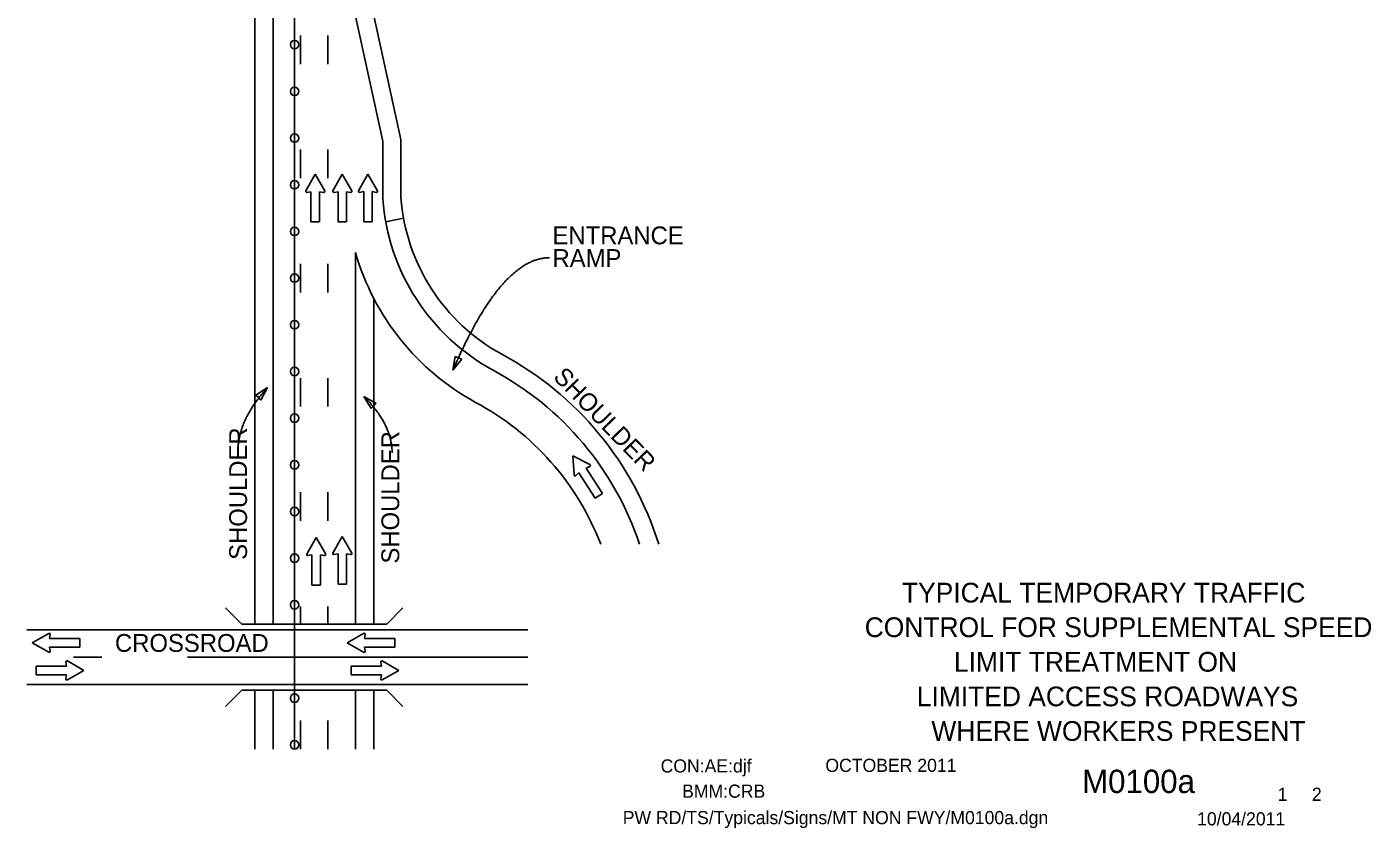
# Model space of a CAD drawing. Extents: x 16115 to 18454, y 4946 to 8326.
# Drawn here: x 16792 to 17425, y 7218 to 7596 of the extents above; entities that cross this region are included whole.
import ezdxf

# ---------------------------------------------------------------- set-up
doc = ezdxf.new("R2010")
doc.units = 0
for name, color, linetype in [('BORDER', 7, 'Continuous'), ('BORDER_SIGNAL_WO', 7, 'Continuous'), ('MT_SCRATCH_LEVEL_E', 7, 'Continuous'), ('PAVT_EDGE_EX', 7, 'Continuous'), ('SCRATCH_LEVEL_A', 7, 'Continuous'), ('TRAFFIC_SIGNS_PR', 7, 'Continuous')]:
    doc.layers.add(name, color=color, linetype=linetype)

msp = doc.modelspace()

# ---------------------------------------------------------------- linework, layer by layer
at = {"layer": 'BORDER'}
for p, q in [((16961.22, 7503.82), (16969.66, 7505.53)), ((16993.91, 7440.44), (16992.85, 7433.9)), ((16995.46, 7439.74), (16993.91, 7440.44)), ((16997.01, 7439.05), (16995.46, 7439.74)), ((16992.85, 7433.9), (16997.01, 7439.05)), ((16905.56, 7425.72), (16899.98, 7422.15)), ((16899.98, 7422.15), (16901.23, 7421.01)), ((16901.23, 7421.01), (16902.48, 7419.86)), ((16902.48, 7419.86), (16905.56, 7425.72)), ((16950.98, 7421.53), (16954.31, 7415.8)), ((16956.71, 7418.2), (16950.98, 7421.53)), ((16954.31, 7415.8), (16955.51, 7417)), ((16955.51, 7417), (16956.71, 7418.2))]:
    msp.add_line(p, q, dxfattribs=at)
msp.add_lwpolyline([(16918.32, 7255.33), (16918.32, 8189.12)], dxfattribs=at)
for centre in [(16918.32, 7587.33), (16918.32, 7565.33), (16918.32, 7543.33), (16918.32, 7521.33), (16918.32, 7499.33), (16918.32, 7477.33), (16918.32, 7455.33), (16918.32, 7433.33), (16918.32, 7411.33), (16918.32, 7389.33), (16918.32, 7367.33), (16918.32, 7345.33), (16918.32, 7323.33), (16918.32, 7279.33), (16918.32, 7257.33)]:
    msp.add_circle(centre, 2, dxfattribs=at)
for points in [[(16992.89, 7433.94), (17015.61, 7486.89), (17038.33, 7486.89)], [(16905.56, 7425.72), (16891.59, 7410.52), (16891.59, 7395.33)], [(16950.98, 7421.53), (16964.25, 7408.25), (16964.25, 7394.98)]]:
    msp.add_open_spline(points, degree=2, dxfattribs=at)
at = {"layer": 'MT_SCRATCH_LEVEL_E'}
for p, q in [((16928.03, 7526.22), (16923.6, 7518.43)), ((16932.49, 7518.43), (16928.03, 7526.22)), ((16940.76, 7526.22), (16936.34, 7518.43)), ((16945.22, 7518.43), (16940.76, 7526.22)), ((16952.85, 7526.26), (16948.43, 7518.46)), ((16957.32, 7518.46), (16952.85, 7526.26)), ((16924.12, 7517.7), (16926.03, 7518.04)), ((16926.03, 7518.04), (16926.03, 7503.77)), ((16930.06, 7503.77), (16930.06, 7518.04)), ((16930.06, 7518.04), (16931.97, 7517.7)), ((16936.85, 7517.7), (16938.77, 7518.04)), ((16938.77, 7518.04), (16938.77, 7503.77)), ((16942.79, 7503.77), (16942.79, 7518.04)), ((16942.79, 7518.04), (16944.71, 7517.7)), ((16948.95, 7517.73), (16950.86, 7518.07)), ((16950.86, 7518.07), (16950.86, 7503.8)), ((16954.89, 7503.8), (16954.89, 7518.07)), ((16954.89, 7518.07), (16956.8, 7517.73)), ((16926.03, 7503.77), (16930.06, 7503.77)), ((16938.77, 7503.77), (16942.79, 7503.77)), ((16950.86, 7503.8), (16954.89, 7503.8)), ((17057.39, 7389.43), (17049.42, 7393.56)), ((17049.42, 7393.56), (17049.92, 7384.62)), ((17055.56, 7387.78), (17057.36, 7388.53)), ((17050.76, 7384.28), (17052.18, 7385.6)), ((17052.18, 7385.6), (17059.91, 7373.61)), ((17063.3, 7375.79), (17055.56, 7387.78)), ((17059.91, 7373.61), (17063.3, 7375.79)), ((16928.48, 7355.06), (16924.06, 7347.27)), ((16932.94, 7347.27), (16928.48, 7355.06)), ((16940.76, 7355.52), (16936.34, 7347.72)), ((16945.22, 7347.72), (16940.76, 7355.52)), ((16924.58, 7346.53), (16926.49, 7346.87)), ((16926.49, 7346.87), (16926.49, 7332.6)), ((16930.52, 7332.6), (16930.52, 7346.87)), ((16930.52, 7346.87), (16932.43, 7346.53)), ((16936.85, 7346.99), (16938.77, 7347.33)), ((16938.77, 7347.33), (16938.77, 7333.06)), ((16942.79, 7333.06), (16942.79, 7347.33)), ((16942.79, 7347.33), (16944.71, 7346.99)), ((16926.49, 7332.6), (16930.52, 7332.6)), ((16938.77, 7333.06), (16942.79, 7333.06)), ((16802.53, 7309.87), (16794.73, 7305.4)), ((16802.53, 7309.87), (16794.73, 7305.4)), ((16802.93, 7307.44), (16803.26, 7309.35)), ((16802.93, 7307.44), (16803.26, 7309.35)), ((16817.19, 7307.44), (16802.93, 7307.44)), ((16817.19, 7307.44), (16802.93, 7307.44)), ((16817.19, 7303.41), (16817.19, 7307.44)), ((16817.19, 7303.41), (16817.19, 7307.44)), ((16950.82, 7309.87), (16943.03, 7305.4)), ((16950.82, 7309.87), (16943.03, 7305.4)), ((16951.22, 7307.44), (16951.56, 7309.35)), ((16951.22, 7307.44), (16951.56, 7309.35)), ((16965.49, 7307.44), (16951.22, 7307.44)), ((16965.49, 7307.44), (16951.22, 7307.44)), ((16965.49, 7303.41), (16965.49, 7307.44)), ((16965.49, 7303.41), (16965.49, 7307.44)), ((16794.73, 7305.4), (16802.53, 7300.98)), ((16794.73, 7305.4), (16802.53, 7300.98)), ((16803.26, 7301.5), (16802.93, 7303.41)), ((16802.93, 7303.41), (16817.19, 7303.41)), ((16803.26, 7301.5), (16802.93, 7303.41)), ((16802.93, 7303.41), (16817.19, 7303.41)), ((16943.03, 7305.4), (16950.82, 7300.98)), ((16943.03, 7305.4), (16950.82, 7300.98)), ((16951.56, 7301.5), (16951.22, 7303.41)), ((16951.22, 7303.41), (16965.49, 7303.41)), ((16951.56, 7301.5), (16951.22, 7303.41)), ((16951.22, 7303.41), (16965.49, 7303.41)), ((16810.89, 7294.43), (16796.62, 7294.43)), ((16796.62, 7294.43), (16796.62, 7290.4)), ((16810.89, 7294.43), (16796.62, 7294.43)), ((16796.62, 7294.43), (16796.62, 7290.4)), ((16810.55, 7296.34), (16810.89, 7294.43)), ((16810.55, 7296.34), (16810.89, 7294.43)), ((16819.08, 7292.43), (16811.29, 7296.86)), ((16819.08, 7292.43), (16811.29, 7296.86)), ((16959.19, 7294.43), (16944.92, 7294.43)), ((16944.92, 7294.43), (16944.92, 7290.4)), ((16959.19, 7294.43), (16944.92, 7294.43)), ((16944.92, 7294.43), (16944.92, 7290.4)), ((16958.85, 7296.34), (16959.19, 7294.43)), ((16958.85, 7296.34), (16959.19, 7294.43)), ((16967.38, 7292.43), (16959.58, 7296.86)), ((16967.38, 7292.43), (16959.58, 7296.86)), ((16796.62, 7290.4), (16810.89, 7290.4)), ((16796.62, 7290.4), (16810.89, 7290.4)), ((16810.89, 7290.4), (16810.55, 7288.49)), ((16810.89, 7290.4), (16810.55, 7288.49)), ((16811.29, 7287.97), (16819.08, 7292.43)), ((16811.29, 7287.97), (16819.08, 7292.43)), ((16944.92, 7290.4), (16959.19, 7290.4)), ((16944.92, 7290.4), (16959.19, 7290.4)), ((16959.19, 7290.4), (16958.85, 7288.49)), ((16959.19, 7290.4), (16958.85, 7288.49)), ((16959.58, 7287.97), (16967.38, 7292.43)), ((16959.58, 7287.97), (16967.38, 7292.43))]:
    msp.add_line(p, q, dxfattribs=at)
for centre, start, end in [((16924.04, 7518.19), 150.42484, 279.96381), ((16932.05, 7518.19), 260.03619, 29.77312), ((16936.77, 7518.19), 150.42484, 279.96381), ((16944.78, 7518.19), 260.03619, 29.77312), ((16948.87, 7518.22), 150.42484, 279.96381), ((16956.88, 7518.22), 260.03619, 29.77312), ((17057.15, 7388.99), 292.85821, 62.59513), ((17050.42, 7384.65), 183.24686, 312.78582), ((16924.5, 7347.02), 150.42484, 279.96381), ((16932.5, 7347.02), 260.03619, 29.77312), ((16936.77, 7347.48), 150.42484, 279.96381), ((16944.78, 7347.48), 260.03619, 29.77312), ((16802.77, 7309.43), 350.03619, 119.77312), ((16802.77, 7309.43), 350.03619, 119.77312), ((16951.07, 7309.43), 350.03619, 119.77312), ((16951.07, 7309.43), 350.03619, 119.77312), ((16802.77, 7301.42), 240.42484, 9.96381), ((16802.77, 7301.42), 240.42484, 9.96381), ((16951.07, 7301.42), 240.42484, 9.96381), ((16951.07, 7301.42), 240.42484, 9.96381), ((16811.05, 7296.42), 60.42484, 189.96381), ((16811.05, 7296.42), 60.42484, 189.96381), ((16959.34, 7296.42), 60.42484, 189.96381), ((16959.34, 7296.42), 60.42484, 189.96381), ((16811.05, 7288.41), 170.03619, 299.77312), ((16811.05, 7288.41), 170.03619, 299.77312), ((16959.34, 7288.41), 170.03619, 299.77312), ((16959.34, 7288.41), 170.03619, 299.77312)]:
    msp.add_arc(centre, 0.498, start, end, dxfattribs=at)
at = {"layer": 'PAVT_EDGE_EX'}
for p, q in [((16899.59, 7715.22), (16899.59, 7314.27)), ((16908.2, 7715.22), (16908.2, 7314.27)), ((16959.83, 7541.84), (16946.95, 7600.76)), ((16968.39, 7542.71), (16955.51, 7601.63)), ((16959.83, 7514.67), (16959.83, 7541.84)), ((16968.41, 7514.67), (16968.41, 7542.71)), ((16946.95, 7489.39), (16946.95, 7314.27)), ((16955.56, 7467.81), (16955.56, 7314.27)), ((16885.79, 7321.88), (16893.4, 7314.27)), ((16969.36, 7321.88), (16961.75, 7314.27)), ((16893.4, 7314.27), (16961.75, 7314.27)), ((16792.22, 7311.58), (17028.08, 7311.58)), ((16792.22, 7285.75), (17028.08, 7285.75)), ((16893.4, 7283.06), (16885.79, 7275.45)), ((16893.4, 7283.06), (16961.75, 7283.06)), ((16899.59, 7283.06), (16899.59, 7255.33)), ((16908.2, 7283.06), (16908.2, 7255.33)), ((16946.95, 7283.06), (16946.95, 7255.33)), ((16955.56, 7283.06), (16955.56, 7255.33)), ((16961.75, 7283.06), (16969.36, 7275.45))]:
    msp.add_line(p, q, dxfattribs=at)
for centre, radius, start, end in [((17060.03, 7522), 91.87, 184.18699, 241.32804), ((17060.03, 7522), 100.47, 184.18699, 241.32804), ((17060.03, 7522), 117.69, 196.08461, 241.32804), ((16943.45, 7306.38), 153.26, 17.2832, 61.76587), ((16943.45, 7306.38), 144.65, 18.34721, 61.79192), ((16943.45, 7306.38), 127.43, 20.93516, 61.85461)]:
    msp.add_arc(centre, radius, start, end, dxfattribs=at)
at = {"layer": 'SCRATCH_LEVEL_A'}
for p, q in [((16959.83, 7541.84), (16959.83, 7541.84)), ((17028.08, 7298.67), (16876.54, 7298.67))]:
    msp.add_line(p, q, dxfattribs=at)
for points in [[(16921.12, 7578.21), (16921.12, 7591.66)], [(16934.03, 7578.21), (16934.03, 7591.66)], [(16921.12, 7524.39), (16921.12, 7537.85)], [(16934.03, 7524.39), (16934.03, 7537.85)], [(16921.12, 7470.58), (16921.12, 7484.03)], [(16934.03, 7470.58), (16934.03, 7484.03)], [(16921.12, 7416.77), (16921.12, 7430.22)], [(16934.03, 7416.77), (16934.03, 7430.22)], [(16921.12, 7362.96), (16921.12, 7376.41)], [(16934.03, 7362.96), (16934.03, 7376.41)], [(16921.12, 7314.27), (16921.12, 7322.6)], [(16934.03, 7314.27), (16934.03, 7322.6)], [(16827.56, 7298.67), (16814.11, 7298.67)], [(16881.38, 7298.67), (16867.92, 7298.67)], [(16876.54, 7298.67), (16881.72, 7298.67)], [(16935.53, 7298.67), (16922.08, 7298.67)], [(16989.35, 7298.67), (16975.89, 7298.67)], [(16921.12, 7255.33), (16921.12, 7268.78)], [(16934.03, 7255.33), (16934.03, 7268.78)]]:
    msp.add_lwpolyline(points, dxfattribs=at)
at = {"layer": 'TRAFFIC_SIGNS_PR'}
msp.add_line((17289.25, 7291.25), (17289.25, 7291.25), dxfattribs=at)

# ---------------------------------------------------------------- texts
at = {"layer": 'BORDER'}
for s, rotation, p in [('ENTRANCE', 360, (17039.78, 7493.24)), ('RAMP', 360, (17039.78, 7482.56)), ('SHOULDER', 314.12305, (17039.68, 7430.3)), ('SHOULDER', 90, (16895.9, 7344.53)), ('SHOULDER', 90, (16967.59, 7342.78)), ('CROSSROAD', 360, (16833.71, 7301.16))]:
    msp.add_text(s, height=8.4, rotation=rotation, dxfattribs=at).set_placement(p)
at = {"layer": 'BORDER_SIGNAL_WO'}
for s, height, p in [('TYPICAL TEMPORARY TRAFFIC', 9.3, (17204.35, 7324.42)), ('CONTROL FOR SUPPLEMENTAL SPEED', 9.3, (17186.82, 7308.12)), ('LIMIT TREATMENT ON', 9.3, (17228.85, 7291.82)), ('LIMITED ACCESS ROADWAYS', 9.3, (17211.35, 7275.52)), ('WHERE WORKERS PRESENT', 9.3, (17218.22, 7259.22)), ('CON:AE:djf', 6.2, (17090.69, 7244.31)), ('    OCTOBER 2011    ', 6.2, (17159.08, 7244.59)), ('    M0100a   ', 11, (17272.86, 7234.63)), ('BMM:CRB   ', 6.2, (17100.81, 7232.42)), (' 1     2', 6.2, (17379.02, 7230.95)), (' PW RD/TS/Typicals/Signs/MT NON FWY/M0100a.dgn ', 6.2, (17070.55, 7219.96)), ('10/04/2011    ', 6.2, (17343.38, 7219.38))]:
    msp.add_text(s, height=height, dxfattribs=at).set_placement(p)

doc.saveas('drawing.dxf')
